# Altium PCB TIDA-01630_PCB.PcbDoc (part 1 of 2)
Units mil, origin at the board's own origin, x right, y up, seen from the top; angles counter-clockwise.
Board outline 3155 x 2050 mil, 4 copper layers (Top Layer, Signal Layer 1, Signal Layer 2, Bottom Layer), stack 49.055 mil thick; 119 components, 66 nets, 330 pads, 436 vias.
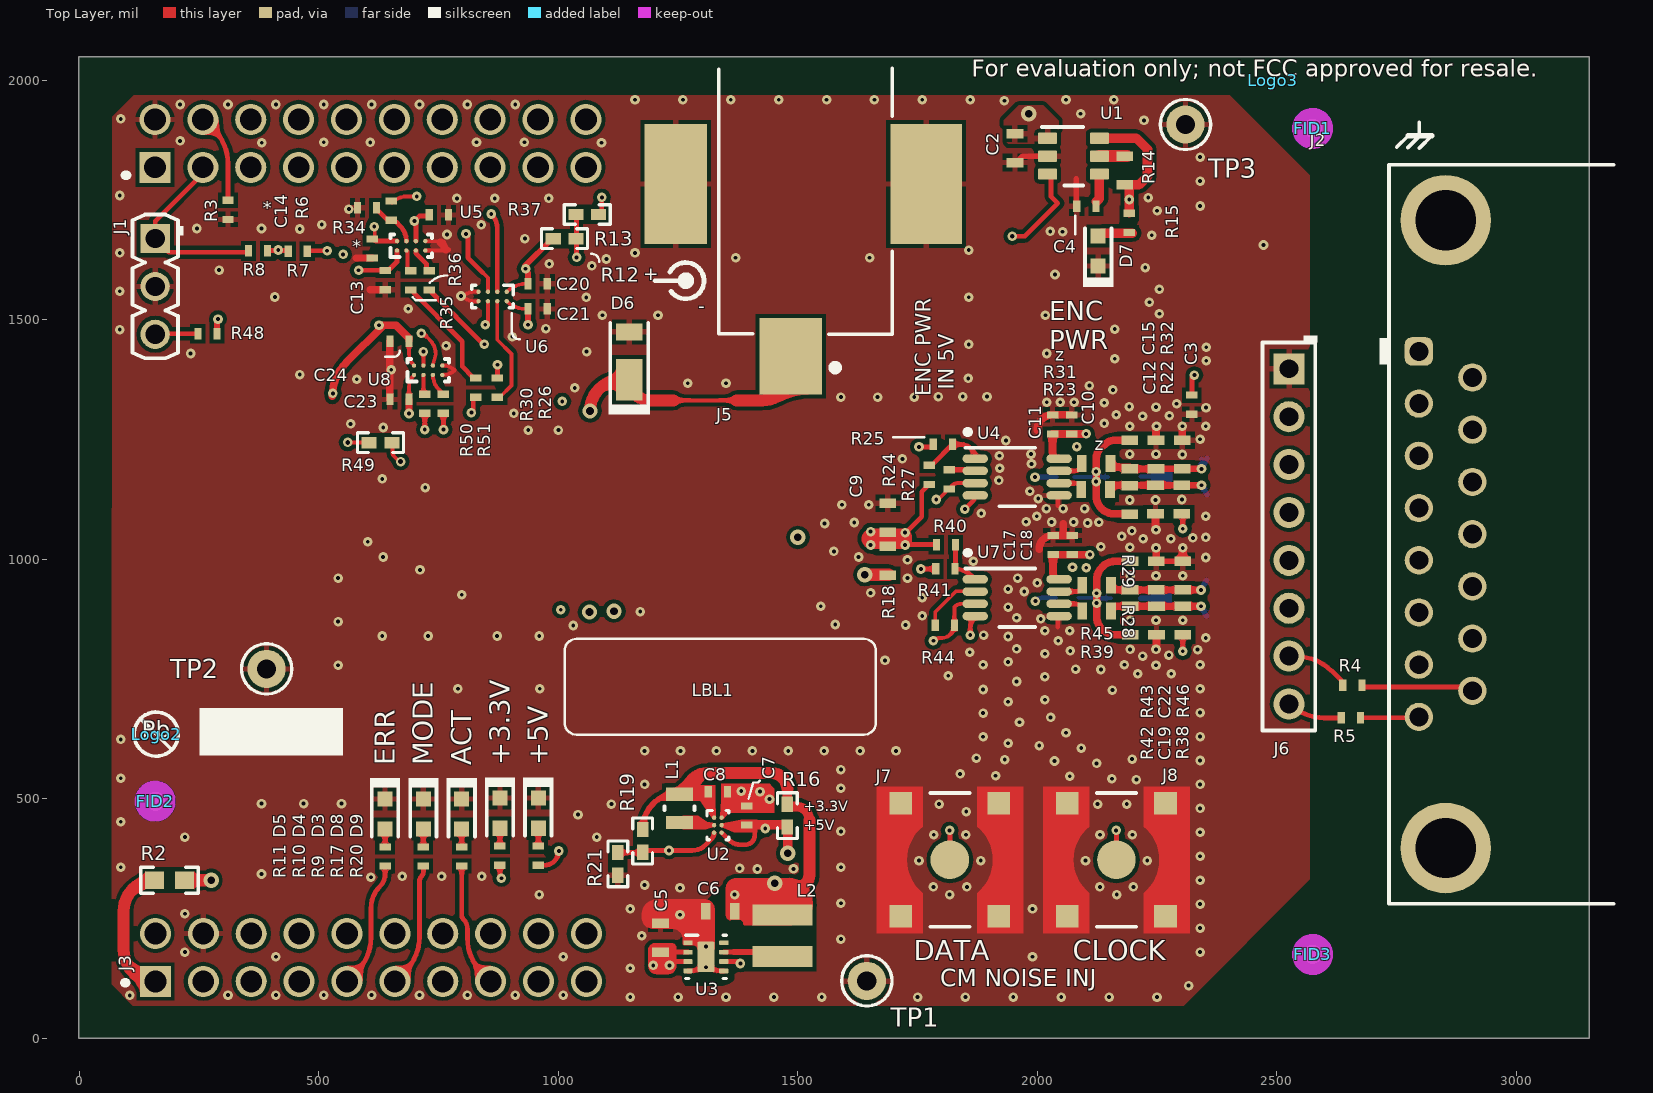
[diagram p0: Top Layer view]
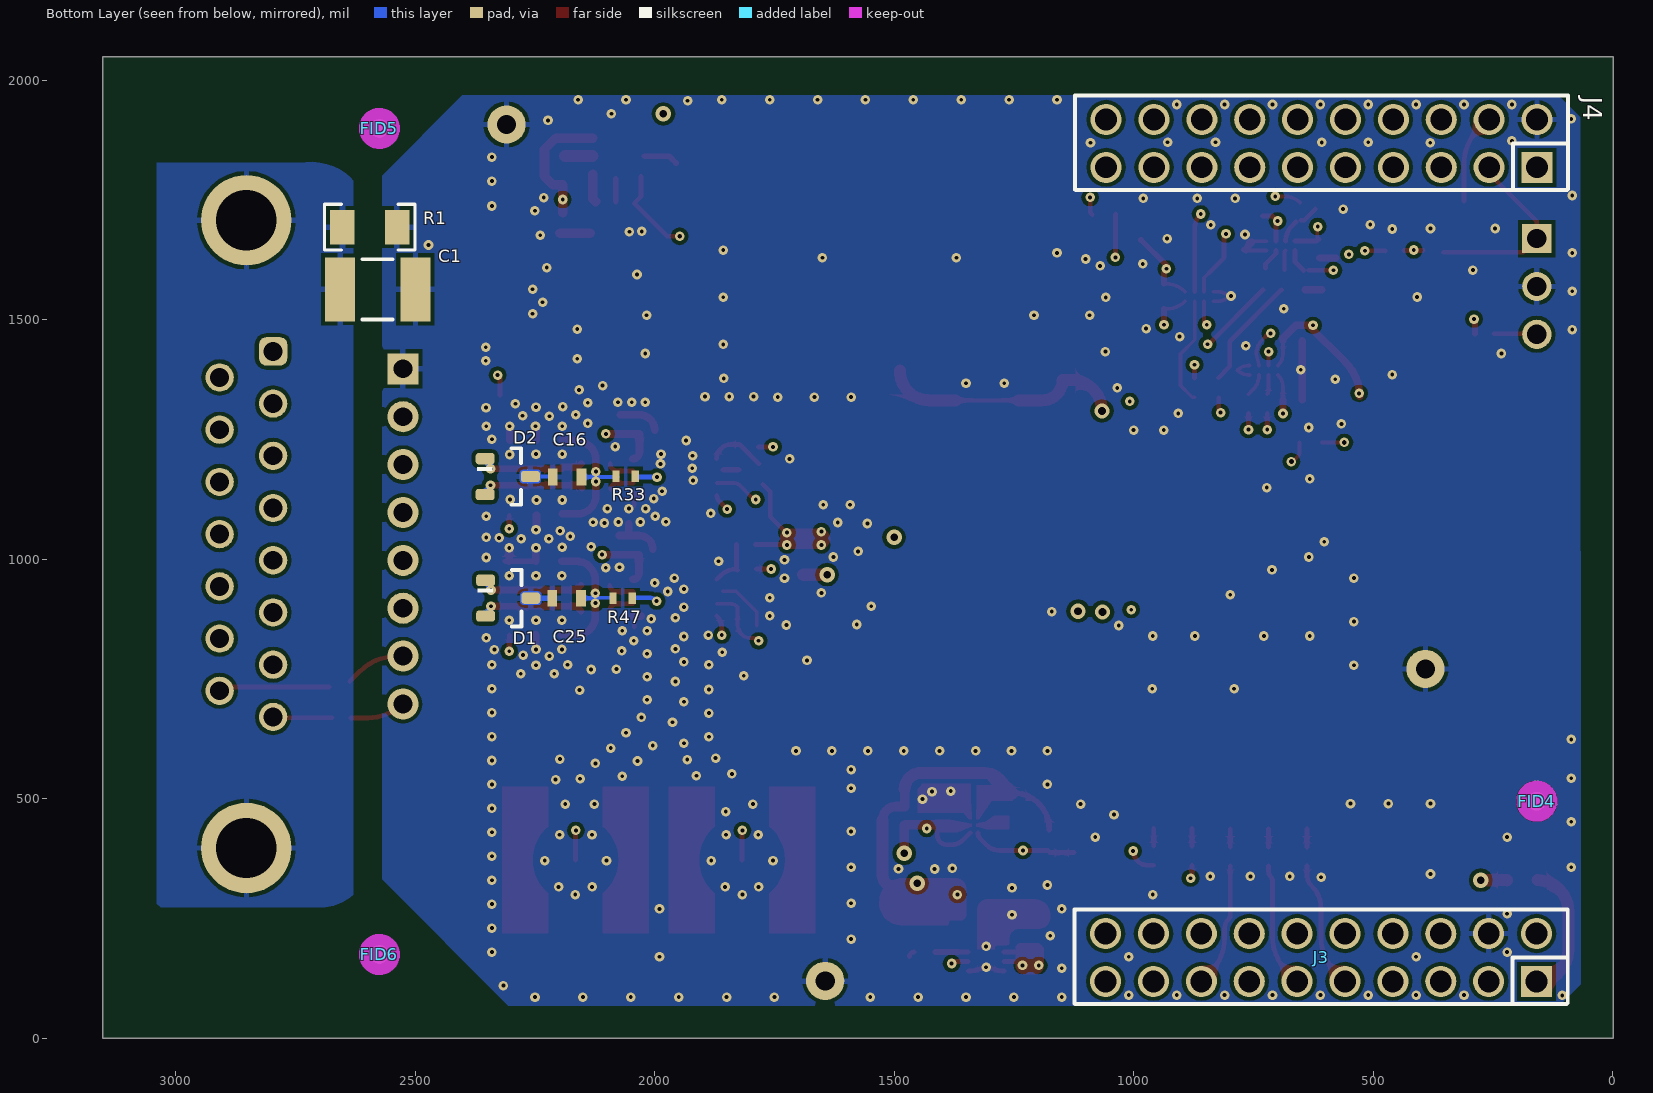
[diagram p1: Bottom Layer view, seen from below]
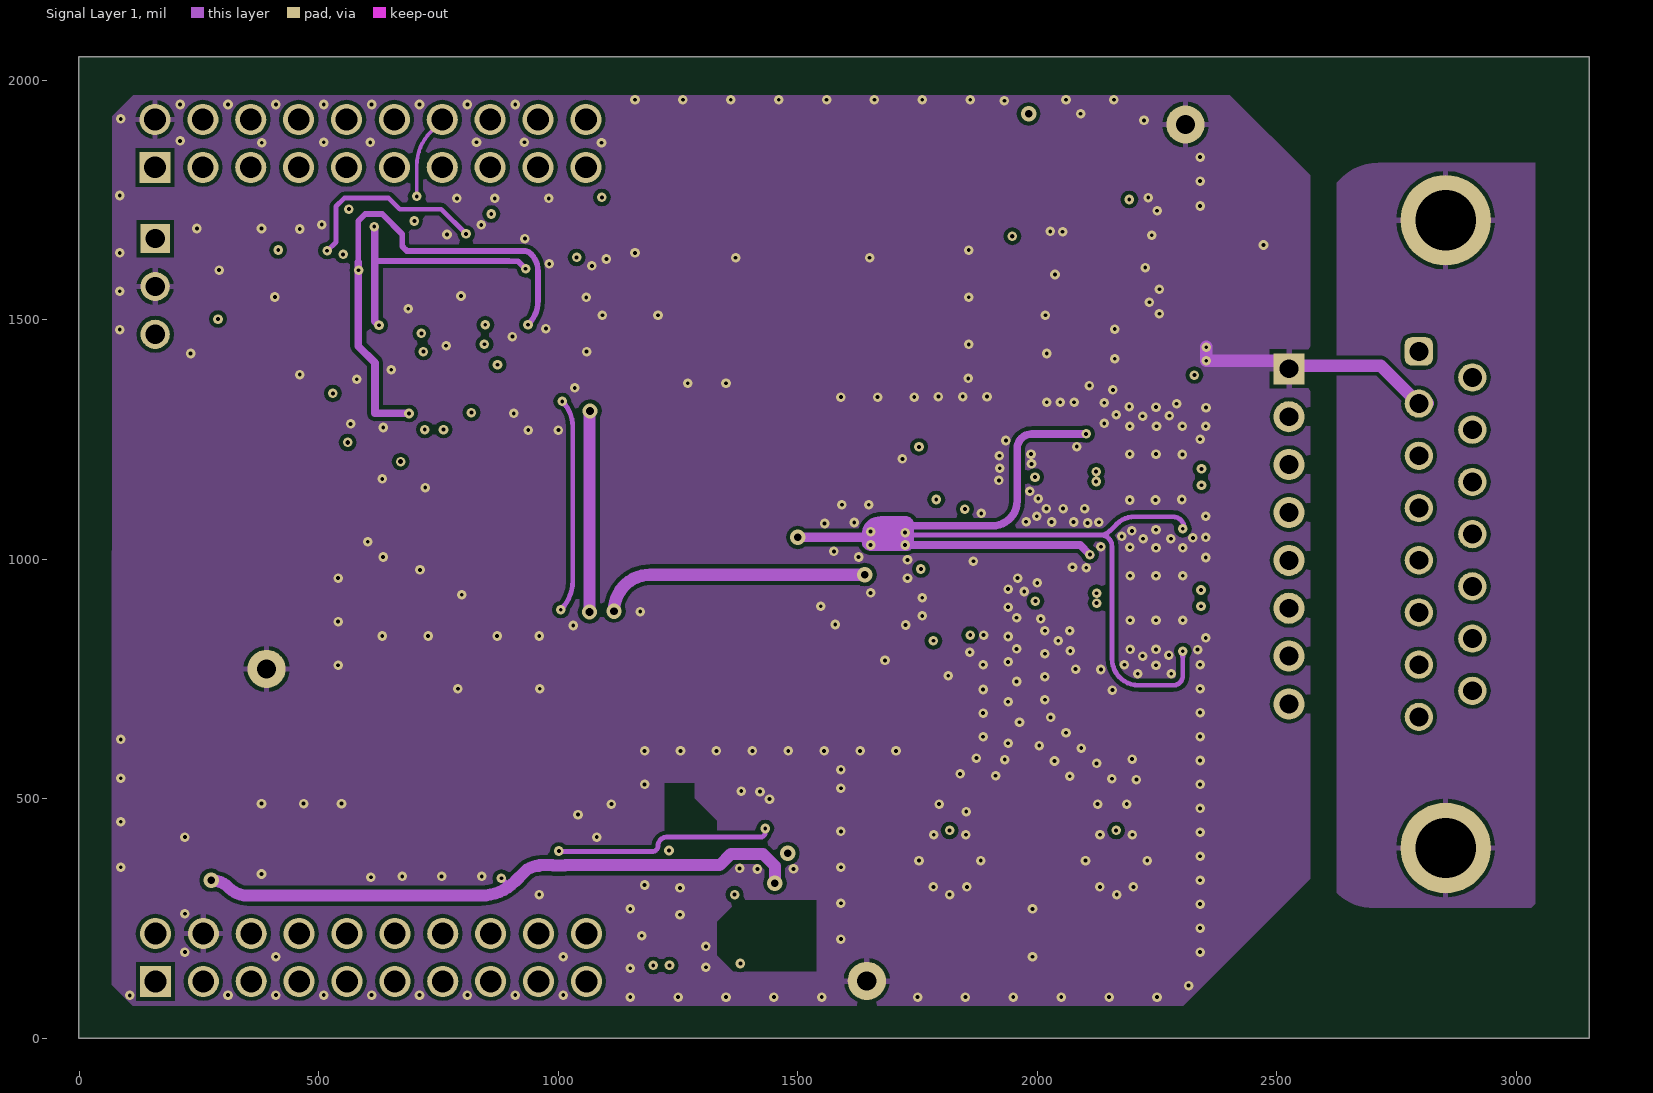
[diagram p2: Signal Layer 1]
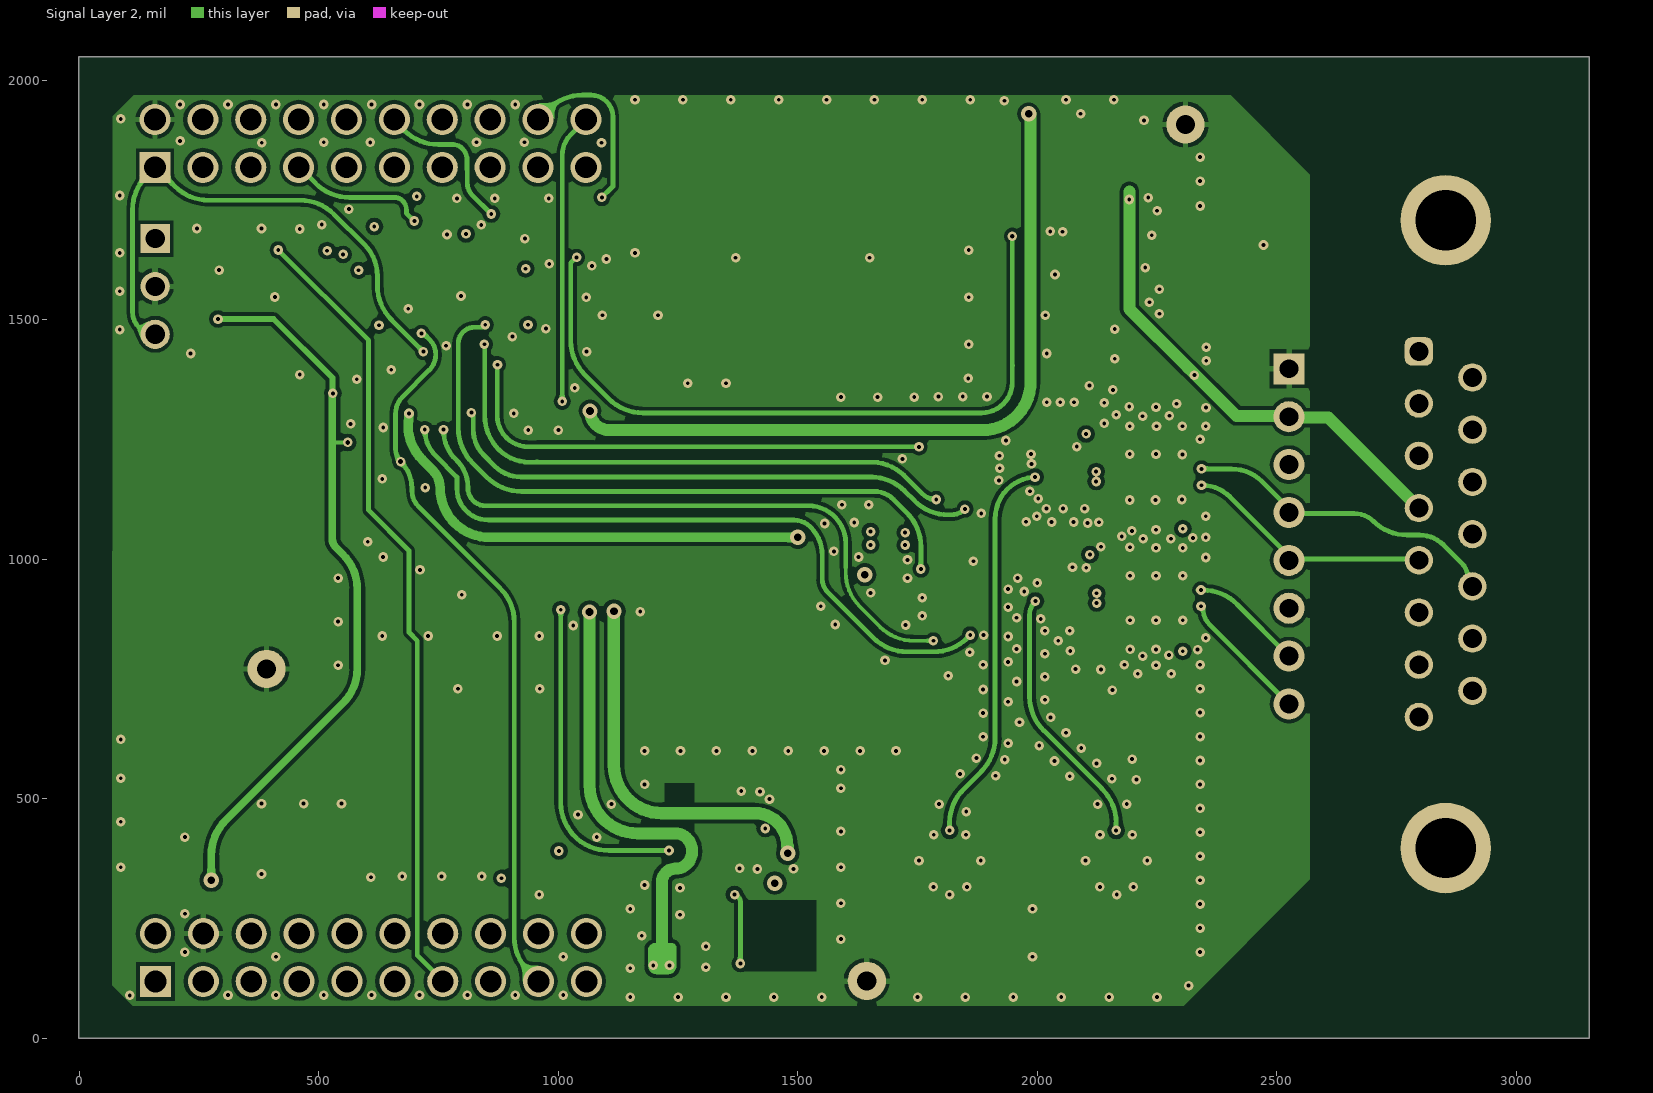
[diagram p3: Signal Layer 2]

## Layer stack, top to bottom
Top Solder: solder mask 0.9843, Solder Resist, Dk 3.5
Top Layer: signal copper 1.6929
Dielectric 1: prepreg 7.4803, FR-4, Dk 4.3
Signal Layer 1: signal copper 1.378
Dielectric 2: core 27.9528, FR-4, Dk 4.3
Signal Layer 2: signal copper 1.378
Dielectric 3: prepreg 7.4803, FR-4, Dk 4.3
Bottom Layer: signal copper 1.6929
Bottom Solder: solder mask 0.9843, Solder Resist, Dk 3.5

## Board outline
-2,0 3153,0 3153,2050 -2,2050

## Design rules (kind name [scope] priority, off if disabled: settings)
AcuteAngle [All] p1: minimum=3.00000000000000E+0001 checktracksonly=FALSE
AssemblyTestPointUsage [All] p1: valid=2
BoardOutlineClearance BoardOutlineClearance_MountingHoles [OnCopper and InComponentClass('Mounting Holes')] p1: gap=40 ignorepadtopadclearanceinfootprint=FALSE
BoardOutlineClearance BoardOutlineClearance_Poly [OnCopper and IsPoly] p2: gap=25 ignorepadtopadclearanceinfootprint=FALSE
BoardOutlineClearance [OnCopper and Not InComponentClass('Logo') and not InComponentClass('FiducialMark') and not InRegion(1000,500,4000,800) and not InPoly] p3: gap=75 ignorepadtopadclearanceinfootprint=FALSE
Clearance Clearance_partu4_u7 [((Component =U4)or (Component= U7))] p1: gap=7.8 ignorepadtopadclearanceinfootprint=FALSE except(0: Arc-Hole Track-Hole SMDPad-Hole THPad-Hole Via-Hole Fill-Hole Poly-Hole Region-Hole Text-Hole)
Clearance Clearance_partu2 [((Component =U2))] p2: gap=6.2 ignorepadtopadclearanceinfootprint=FALSE except(0: Arc-Hole Track-Hole SMDPad-Hole THPad-Hole Via-Hole Fill-Hole Poly-Hole Region-Hole Text-Hole)
Clearance Clearance_fiducial [((Component =FID1) or (Component =FID2) or (Component =FID3) or (Component =FID4) or (Component =FID5) or (Component =FID6))] p3: gap=0 ignorepadtopadclearanceinfootprint=FALSE
Clearance Clearance_netsu2 [(Net = '3V3') or (Net = '3V3_ENABLE_5V') vs (Net = 'NetL1_2') or (Net = '5VUNFILTERED')] p4: gap=5.7 ignorepadtopadclearanceinfootprint=FALSE except(0: Arc-Hole Track-Hole SMDPad-Hole THPad-Hole Via-Hole Fill-Hole Poly-Hole Region-Hole Text-Hole)
Clearance Clearance_Keepouts [((IsTrack Or IsArc) And Not InPoly) And IsFree and IsKeepOut vs ((IsTrack Or IsArc) And Not InPoly) And IsFree and IsKeepOut] p5: gap=0 ignorepadtopadclearanceinfootprint=FALSE
Clearance Clearance_Poly [InPolygon] p6: gap=8 ignorepadtopadclearanceinfootprint=FALSE except(0: Arc-Hole Track-Hole SMDPad-Hole THPad-Hole Via-Hole Fill-Hole Poly-Hole Region-Hole Text-Hole)
Clearance Clearance_part [Not IsNetTieComponent vs Not IsNetTieComponent] p7: gap=8 ignorepadtopadclearanceinfootprint=FALSE except(0: Arc-Hole Track-Hole SMDPad-Hole THPad-Hole Via-Hole Fill-Hole Poly-Hole Region-Hole Text-Hole)
ComponentClearance ComponentClearance_MountingHoles_FiducialMarks [InComponentClass('Mounting Holes') vs InComponentClass('FiducialMark')] p1: gap=50 collisioncheckmode=3 verticalgap=10 showdistances=FALSE
ComponentClearance ComponentClearance_Shunt [InComponentClass('Header') vs InComponentClass('Shunt')] p2: gap=0 collisioncheckmode=3 verticalgap=0 showdistances=FALSE
ComponentClearance ComponentClearance_Logo [InComponentClass('Logo')] p3: gap=20 collisioncheckmode=3 verticalgap=10 showdistances=FALSE
ComponentClearance ComponentClearance_ScrewToNut [(HasFootprint('NY PMS 440 0025 PH')) vs (HasFootprint('Keystone_1902C'))] p4: gap=5 collisioncheckmode=3 verticalgap=10 showdistances=FALSE
ComponentClearance ComponentClearance_MountingHoles [InComponentClass('Mounting Holes')] p5: gap=250 collisioncheckmode=3 verticalgap=100000 showdistances=FALSE
ComponentClearance ComponentClearance_SmallPassives [HasFootprint('0201*') or HasFootprint('0402*') or HasFootprint('0508') or HasFootprint('0603*') or HasFootprint('0612') or HasFootprint('0805*') or HasFootprint('0815*') or HasFootprint('0830*') or HasFootprint('1206*') or HasFootprint('1210*') or HasFootprint('1808*') or HasFootprint('1812*') or HasFootprint('1825*') or HasFootprint('2010*') or HasFootprint('2220*') or HasFootprint('2225*') or HasFootprint('2512*') or HasFootprint('2728*') or HasFootprint('3518*') vs HasFootprint('0201*') or HasFootprint('0402*') or HasFootprint('0508') or HasFootprint('0603*') or HasFootprint('0612') or HasFootprint('0805*') or HasFootprint('0815*') or HasFootprint('0830*') or HasFootprint('1206*') or HasFootprint('1210*') or HasFootprint('1808*') or HasFootprint('1812*') or HasFootprint('1825*') or HasFootprint('2010*') or HasFootprint('2220*') or HasFootprint('2225*') or HasFootprint('2512*') or HasFootprint('2728*') or HasFootprint('3518*')] p6: gap=14.96 collisioncheckmode=3 verticalgap=10 showdistances=FALSE
ComponentClearance ComponentClearance_THtoSMT [IsThruComponent vs IsSMTComponent] p7: gap=15 collisioncheckmode=3 verticalgap=30 showdistances=FALSE
ComponentClearance ComponentClearance_THtoTH [IsThruComponent vs IsThruComponent] p8: gap=30 collisioncheckmode=3 verticalgap=30 showdistances=FALSE
ComponentClearance [Not IsNetTieComponent vs Not IsNetTieComponent] p9: gap=30 collisioncheckmode=3 verticalgap=10 showdistances=FALSE
DiffPairsRouting [All] p1: maxlimit=100 minlimit=10 mostfreqgap=10 toplayer_minwidth=10 toplayer_maxwidth=15 toplayer_prefwidth=15 midlayer1_minwidth=10 midlayer1_maxwidth=15 midlayer1_prefwidth=15 midlayer2_minwidth=10 midlayer2_maxwidth=15 midlayer2_prefwidth=15 bottomlayer_minwidth=10 bottomlayer_maxwidth=15 bottomlayer_prefwidth=15 maxuncoupledlength=1000
FabricationTestPointUsage TestPointUsage [All] p1: valid=2 allowmultiple=FALSE
FabricationTestpoint Testpoint [All] p1: side=3 testpointundercomponent=TRUE minsize=40 maxsize=100 preferedsize=60 minholesize=0 maxholesize=40 preferedholesize=32 testpointgrid=1 allowsidetop=TRUE allowsidebottom=TRUE usegrid=TRUE gridtolerance=0.01
FanoutControl Fanout_LCC [IsLCC] p1: bgadir=Out bgaviamode=Centered fanoutstyle=Auto fanoutdirection=Alternating viagrid=1 // Fanout_LCC (Default Rule)
FanoutControl Fanout_BGA [IsBGA] p2: bgadir=Out bgaviamode=Centered fanoutstyle=Auto fanoutdirection=Alternating viagrid=1 // Fanout_BGA (Default Rule)
FanoutControl Fanout_Default [All] p4: bgadir=Out bgaviamode=Centered fanoutstyle=Auto fanoutdirection=Alternating viagrid=1 // Fanout_Default (Default Rule)
FanoutControl Fanout_Small [(CompPinCount < 5)] p5: bgadir=Out bgaviamode=Centered fanoutstyle=Auto fanoutdirection=OutThenIn viagrid=1 // Fanout_Small (Default Rule)
HoleSize [All] p1: absolutevalues=TRUE maxlimit=251 minlimit=7.87 maxpercent=80.000 minpercent=20.000
HoleToHoleClearance [All] p1: gap=10 allowstackedmicrovias=FALSE
MinimumAnnularRing MinimumAnnularRing_ThermalPadVias [IsVia and InAnyComponent] p1: minimumring=5
MinimumAnnularRing [All] p2: minimumring=5
MinimumSolderMaskSliver MinimumSolderMaskSliver_Logo [InComponentClass('Logo') vs InComponentClass('Logo')] p1: minsoldermaskwidth=0.7
MinimumSolderMaskSliver [All] p2: minsoldermaskwidth=2
NetAntennae [All] p1: netantennaetolerance=4
PlaneClearance [All] p1: clearance=10
PlaneConnect [All] p1: planeconnectstyle=Relief reliefexpansion=10 reliefentries=4 reliefconductorwidth=14 reliefairgap=8
PolygonConnect PolygonConnect_Power [IsVia  Or InLayerStackRegion('')] p1: connectstyle=Direct reliefconductorwidth=10 reliefentries=4 polygonreliefangle="90 Angle" airgapwidth=10
PolygonConnect [All] p2: connectstyle=Relief reliefconductorwidth=12 reliefentries=4 polygonreliefangle="90 Angle" airgapwidth=8
RoutingCorners [All] p1: cornerstyle=Round minsetback=100 maxsetback=100
RoutingVias ThermalPadVias [IsVia and InAnyComponent] p1: holewidth=8 width=20 viastyle="Through Hole" minholewidth=7.87 minwidth=18 maxholewidth=13 maxwidth=24
RoutingVias [All] p2: holewidth=10 width=20 viastyle="Through Hole" minholewidth=7.87 minwidth=18 maxholewidth=40 maxwidth=60
SilkToBoardRegionClearance [Not ((IsComment or IsDesignator) And (Hide <> 'False')) and not InRegion(1000,500,4000,800)] p1:
SilkToSilkClearance SilkToSilkClearance_Pb-FreeLogo [(HasFootprint('Pb-Free_Overlay_Medium') OR HasFootprint('Pb-Free_Overlay_Small')) vs (HasFootprint('Pb-Free_Overlay_Medium') OR HasFootprint('Pb-Free_Overlay_Small'))] p1: silktosilkclearance=0
SilkToSilkClearance [All] p2: silktosilkclearance=2
SilkToSolderMaskClearance [InNet('NetC24_1') Or InNet('NetC15_1')] p1: minsilkscreentomaskgap=0 clearancetoexposedcopper=TRUE
SilkToSolderMaskClearance SilkToComponentPadClearance [(IsPad or IsFill or IsRegion) and InAnycomponent] p2: minsilkscreentomaskgap=3 clearancetoexposedcopper=TRUE
SilkToSolderMaskClearance "Silk to Solder Mask Opening" [All] p3: minsilkscreentomaskgap=2 clearancetoexposedcopper=FALSE
SolderMaskExpansion [All] p1: expansion=1.97
ViasUnderSMD [IsNetTieComponent] p1: allowed=TRUE
Width [All] p1: maxlimit=100 minlimit=6 preferedwidth=10 checkconnectedcopper=TRUE
11 further rules are at their usual default settings.

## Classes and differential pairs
component class TIDA-01630_Transceivers: C10 C11 C12 C13 C14 C15 C16 C17 C18 C19 C20 C21 C22 C23 C24 C25 C28 J7 J8 NT? R22 R23 R24 R25 R26 R27 R28 R29 R30 R31 R32 R33 R34 R35 R36 R37 R38 R39 R40 R41 R42 R43 R44 R45 R46 R47 R48 R49 R50 R51 U4 U5 U6 U7 U8
component class TIDA-01630_PowerSupply: C2 C3 C4 C5 C6 C7 C8 C9 D7 D8 D9 L1 L2 R12 R13 R14 R15 R16 R17 R18 R19 R20 R21 U1 U2 U3
component class TIDA-01630_Interface: C1 D1 D2 D3 D4 D5 D6 J1 J2 J3 J4 J5 J6 R1 R2 R3 R4 R5 R6 R7 R8 R9 R10 R11 TP1 TP2 TP3
component class Header: J1 J6
component class Label: LBL1
component class AssemblyNote: ZZ1 ZZ2 ZZ3 ZZ4
component class FiducialMark: FID1 FID2 FID3 FID4 FID5 FID6
component class TIDA-01630_EVM_Hardware: FID1 FID2 FID3 FID4 FID5 FID6 LBL1 Logo2 Logo3 ZZ1 ZZ2 ZZ3 ZZ4
differential pair D_CLK_: +CLK_P -CLK_N
differential pair D_DATA_: +DATA_P -DATA_N

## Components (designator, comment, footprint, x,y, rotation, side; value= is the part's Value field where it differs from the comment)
C1 "1812GC102KAT1A" 1812_220 2578.61,1564.03 r180 bottom value=1000pF
C2 "Capacitor" 0603S 1953.42,1858.66 r270 top value=1uF
C3 "GRM155R6YA225ME11D" 0402_070 2323,1323 r270 top value=2.2uF
C4 "GRM155R71H471KA01D" 0402S 2102.59,1737.67 r0 top value=470pF
C5 "Capacitor" 0603S 1213,210 r90 top value=10uF
C6 "Capacitor" 0603S 1338,265 r180 top value=22uF
C7 "Capacitor" 0402_065S 1393,465 r90 top value=4.7uF
C8 "885012105013" 0402S 1333,515 r0 top value=2.2uF
C9 "Capacitor" 0603S 1688,1087 r90 top value=22uF
C10 "Capacitor" 0402S 2072,1281.76 r90 top value=1uF
C11 "Capacitor" 0402S 2032,1281.76 r90 top value=0.1uF
C12 "Capacitor" 0603S 2247,1125 r90 top value=220pF
C13 "Capacitor" 0402S 638.49,1583.17 r90 top value=0.1uF
C14 "Capacitor" 0402S 611.37,1649.31 r90 top value=0.1uF
C15 "Capacitor" 0603S 2248,1219 r90 top value=220pF
C16 "Capacitor" 0603S 2183,1172 r0 bottom value=470pF
C17 "Capacitor" 0402S 2033,1030 r90 top value=1uF
C18 "Capacitor" 0402S 2073,1030 r90 top value=0.1uF
C19 "Capacitor" 0603S 2249,872.33 r90 top value=220pF
C20 "Capacitor" 0402S 956.54,1575.55 r180 top value=0.1uF
C21 "Capacitor" 0402S 956.54,1523.05 r180 top value=0.1uF
C22 "Capacitor" 0603S 2248.73,966.16 r90 top value=220pF
C23 "Capacitor" 0402S 668,1334 r0 top value=0.1uF
C24 "Capacitor" 0402S 668,1456 r0 top value=0.1uF
C25 "Capacitor" 0603S 2184,919 r0 bottom value=470pF
D1 "Diode_TVS_Bi_Dual" SOT-23 2306,919 r180 bottom value=7V
D2 "Diode_TVS_Bi_Dual" SOT-23 2307,1173 r180 bottom value=7V
D3 "LED_A2_K1" WL-SMCW_Blue 798,468.37 r270 top value=Blue
D4 "LED_A2_K1" WL-SMCW_GREEN 718,468.37 r270 top value=Green
D5 "LED_A2_K1" WL-SMCW_RED 638,468.37 r270 top value=Red
D6 "DIODE" PowerDI123 1148,1425 r90 top value=40V
D7 "LED_A2_K1" WL-SMCW_GREEN 2127.3,1644.02 r90 top value=Green
D8 "LED_A2_K1" WL-SMCW_GREEN 878,470 r270 top value=Green
D9 "LED_A2_K1" WL-SMCW_GREEN 958,470 r270 top value=Green
FID1 "Fiducial" Fiducial10-20 2575,1900 r0 top
FID2 "Fiducial" Fiducial10-20 158,495 r0 top
FID3 "Fiducial" Fiducial10-20 2575,175 r0 top
FID4 "Fiducial" Fiducial10-20 158,495 r180 bottom
FID5 "Fiducial" Fiducial10-20 2575,1900 r180 bottom
FID6 "Fiducial" Fiducial10-20 2575,175 r180 bottom
J1 "Header_3x1" FCI_68001-403HLF 158,1570 r270 top
J2 "618015231121" Wurth_618015231121 3226.83,1052.73 r0 top
J3 "Receptacle_10x2" CONN_SSW-110-23-F-D 608.49,168.62 r180 bottom locked
J4 "Receptacle_10x2" CONN_SSW-110-23-F-D 607.49,1868.62 r180 bottom
J5 "CONN_DC JACK" Switchcraft_RASM722 1515,2050 r180 top
J6 "Header_8x1" SULLINS_PEC08SAAN 2525.63,1047.98 r270 top
J7 "SMA_Contact1_GND2345" Linx_CONSMA001-SMD-G 1817.59,372.51 r0 top
J8 "SMA_Contact1_GND2345" Linx_CONSMA001-SMD-G 2165.34,372.51 r180 top
L1 "Inductor_Iron" WE-PMI_0805LR 1253,480 r270 top value=1uH
L2 "Inductor_Iron" XFL3012 1468,214 r90 top value=2.2uH
LBL1 "Label" Label_650x200 1338,734 r0 top
Logo2 "Pb-Free Symbol" Pb-Free_Overlay_Small 160,635 r0 top
Logo3 "FCC disclaimer" FCC_disclaimer 2491.49,2000.85 r0 top
R1 "Resistor" 1206 2595.31,1693.75 r0 bottom value=2.2Meg
R2 "Resistor" 0603 188,330 r180 top value=0
R3 "Resistor" 0402S 310,1730 r270 top value=150k
R4 "Resistor" 0402S 2658.08,737.24 r180 top value=0
R5 "Resistor" 0402S 2654.82,669.45 r0 top value=0
R6 "CRCW040222R0JNED" 0402S 650.59,1728.19 r270 top value=22
R7 "CRCW040222R0JNED" 0402S 455.66,1643.76 r180 top value=22
R8 "Resistor" 0402S 372.78,1644.13 r180 top value=0
R9 "Resistor" 0402S 798,379.57 r270 top value=2.2k
R10 "Resistor" 0402S 718,379.57 r270 top value=2.2k
R11 "Resistor" 0402S 638,379.57 r270 top value=4.7k
R12 "Resistor" 0402 1012.79,1669.73 r180 top value=10k
R13 "Resistor" 0402 1060.41,1720.32 r180 top value=0
R14 "Resistor" 0603S 2182.96,1812.11 r270 top value=1.0k
R15 "Resistor" 0402S 2192.45,1702.78 r270 top value=30k
R16 "Resistor" 0402 1478,465 r90 top value=0
R17 "Resistor" 0402S 878,381.2 r270 top value=2.2k
R18 "Resistor" 0603S 1688,997 r90 top value=1.0
R19 "Resistor" 0402 1176,412 r90 top value=10k
R20 "Resistor" 0402S 958,381.2 r270 top value=4.7k
R21 "Resistor" 0402 1124,364 r90 top value=10k
R22 "CRCW06031K00JNEA" 0603S 2302,1125 r270 top value=1.0k
R23 "Resistor" 0603S 2122,1146 r0 top value=0
R24 "CRCW04024K70JNED" 0402S 1774.43,1176.56 r270 top value=4.7k
R25 "CRCW040222R0JNED" 0402S 1803,1240 r0 top value=22
R26 "Resistor" 0402S 872.71,1358.65 r90 top value=0
R27 "Resistor" 0402S 1816.58,1167.15 r90 top value=0
R28 "CRCW0603110RFKEA" 0603S 2193,1124 r90 top value=110
R29 "CRCW0603110RFKEA" 0603S 2193,1219 r90 top value=110
R30 "Resistor" 0402S 827.7,1358.65 r270 top value=0
R31 "Resistor" 0603S 2123,1200 r0 top value=0
R32 "CRCW06031K00JNEA" 0603S 2303,1219 r270 top value=1.0k
R33 "Resistor" 0402S 2060.72,1173.24 r0 bottom value=0
R34 "CRCW04024K70JNED" 0402S 600.29,1734.26 r180 top value=4.7k
R35 "Resistor" 0402S 691.17,1582.87 r90 top value=47
R36 "Resistor" 0402S 730.17,1582.87 r90 top value=47
R37 "CRCW04024K70JNED" 0402S 750.37,1719.29 r180 top value=4.7k
R38 "Resistor" 0603S 2304,872.33 r270 top value=10k
R39 "Resistor" 0603S 2124,892 r0 top value=0
R40 "CRCW04024K70JNED" 0402S 1809.43,1030.82 r180 top value=4.7k
R41 "CRCW040222R0JNED" 0402S 1808,980 r0 top value=22
R42 "Resistor" 0603S 2194,872.33 r270 top value=59.0
R43 "Resistor" 0603S 2193.73,966.16 r270 top value=59.0
R44 "Resistor" 0402S 1807,862 r180 top value=0
R45 "Resistor" 0603S 2124,946 r0 top value=0
R46 "Resistor" 0603S 2303.73,966.16 r270 top value=10k
R47 "Resistor" 0402S 2067.02,919.24 r0 bottom value=0
R48 "CRCW04024K70JNED" 0402S 267.15,1471.32 r0 top value=4.7k
R49 "CRCW04024K70JNED" 0402 628.47,1243.65 r180 top value=4.7k
R50 "Resistor" 0402S 721,1325 r90 top value=47
R51 "Resistor" 0402S 760,1325 r90 top value=47
TP1 "5001" Keystone5001 1644.09,119.71 r90 top
TP2 "5001" Keystone5001 390.6,771.25 r90 top
TP3 "5001" Keystone5001 2309.52,1908.2 r90 top
U1 "TPS22810DBV" DBV0006A_N 2075.73,1842.05 r0 top
U2 "TPS6124xYFF" YFF0006AEAE 1333,445 r0 top
U3 "TI-TPS62162DSG8-1600X900TP" DSG0008A 1308,170 r0 top
U4 "THVD1550DGKR" DGK0008A_N 1958,1172 r0 top
U5 "TI-SN74XVC2T45-YZP0008A-8" YZP0008ADAD 692.49,1654.86 r90 top
U6 "TI-SN74XVC2T45-YZP0008A-8" YZP0008ADAD 862.54,1549.05 r270 top
U7 "THVD1550DGKR" DGK0008A_N 1958,920 r0 top
U8 "TI-SN74XVC2T45-YZP0008A-8" YZP0008ADAD 728,1395 r90 top
ZZ1 "This Assembly Note is for PCB labels only" AssemblyNoteLabel 184,3925 r0 top
ZZ2 "These assemblies are ESD sensitive, ESD precautions shall be observed." AssemblyNote 186,3833.11 r0 top
ZZ3 "These assemblies must be clean and free from flux and all contaminants. Use of no clean flux is not acceptable." AssemblyNote 186,3744.56 r0 top
ZZ4 "These assemblies must comply with workmanship standards IPC-A-610 Class 2, unless otherwise specified." AssemblyNote 186,3656 r0 top

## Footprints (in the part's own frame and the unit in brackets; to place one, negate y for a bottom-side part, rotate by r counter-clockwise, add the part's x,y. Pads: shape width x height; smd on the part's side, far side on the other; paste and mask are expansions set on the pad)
0402 [mm] "0402 from SM-752 data"
  rect 0.8x0.6 smd: 1(-0.6,0) 2(0.6,0)
  silkscreen extent -1.22,-0.52 1.22,0.52, body extent -0.55,-0.3 0.55,0.3, height 0.6
0402_065S [mil] "Based on C0402S footprint from PADS legacy"
  rect 15x24 smd: 1(-20,0) 2(20,0)
  body extent -22,-12 22,12, height 26
0402_070 [mil] "SMD, 2-Leads, Body 1.2x0.7mm, Height 0.7mm"
  rect 15x24 smd: 1(-20,0) 2(20,0)
  body extent -24,-14 24,14, height 28
0402S [mil] "Based on C0402S footprint from PADS legacy"
  rect 15x24 smd: 1(-20,0) 2(20,0)
  body extent -22,-12 22,12, height 24
0603 [mm] "0603 from SM-752 data"
  rect 1x0.95 smd: 1(-0.8,0) 2(0.8,0)
  silkscreen extent -1.52,-0.69 1.52,0.69, body extent -0.87,-0.47 0.87,0.47, height 1
0603S [mil]
  rect 20x35 smd: 1(-30,0) 2(30,0)
  body extent -34,-19 34,19, height 39
1206 [mm] "1206 from SM-752 data"
  rect 1.3x1.85 smd: 1(-1.45,0) 2(1.45,0)
  silkscreen extent -2.4,-1.21 2.4,1.21, body extent -1.7,-0.9 1.7,0.9, height 1.35
1812_220 [mm] "1812"
  rect 1.6x3.4 smd: 1(-2,0) 2(2,0)
  silkscreen extent -0.8,-1.6 0.8,1.6, body extent -2.4,-1.7 2.4,1.7, height 2.2
AssemblyNote [mil] "Assembly Note"
AssemblyNoteLabel [mil] "Assembly Note for PCB Labels"
CONN_SSW-110-23-F-D [mm] "SAMTEC"
  rect 1.65x1.65 hole 1.15: 1(11.43,-1.27)
  round 1.65 hole 1.15: 2(11.43,1.27) 3(8.89,-1.27) 4(8.89,1.27) 5(6.35,-1.27) 6(6.35,1.27) 7(3.81,-1.27) 8(3.81,1.27) 9(1.27,-1.27) 10(1.27,1.27) 11(-1.27,-1.27) 12(-1.27,1.27) 13(-3.81,-1.27) 14(-3.81,1.27) 15(-6.35,-1.27) 16(-6.35,1.27) 17(-8.89,-1.27) 18(-8.89,1.27) 19(-11.43,-1.27) 20(-11.43,1.27)
  silkscreen extent -13.08,-2.46 13.08,2.54, body extent -13,-2.51 13,2.54, height 8.59
DBV0006A_N [mm] "SOT23, 6-Leads, Body 2.9x1.6mm, Pitch 0.95mm, Lead Span 2.8mm, IPC Medium Density"
  rrect17% 1x0.6 smd: 1(-1.375,0.95) 2(-1.375,0) 3(-1.375,-0.95) 4(1.375,-0.95) 5(1.375,0) 6(1.375,0.95)
  silkscreen extent -1.68,-1.55 0.5,1.55, body extent -1.42,-1.46 1.42,1.46, height 1.12
DGK0008A_N [mm] "TSOP, 8-Leads, Body 3x3mm, Pitch 0.65mm, IPC Medium Density"
  oval 1.35x0.45 smd: 1(-2.225,0.975) 2(-2.225,0.325) 3(-2.225,-0.325) 4(-2.225,-0.975) 5(2.225,-0.975) 6(2.225,-0.325) 7(2.225,0.325) 8(2.225,0.975)
  silkscreen extent -2.75,-1.55 0.95,1.55, body extent -2.45,-1.5 2.45,1.5, height 0.96
DSG0008A [mm] "SON, 8-Leads, Body 2x2mm, Pitch 0.5mm, Thermal Pad 1.6x0.9mm, TI Recommended"
  rrect40% 0.5x0.25 smd: 1(-0.95,0.75) 2(-0.95,0.25) 3(-0.95,-0.25) 4(-0.95,-0.75) 5(0.95,-0.75) 6(0.95,-0.25) 7(0.95,0.25) 8(0.95,0.75)
  rrect14% 0.9x0.7 on Top Paste: 9(0,-0.45) 9(0,0.45)
  rrect11% 0.9x1.6 smd paste-0.45: 9(0,0)
  silkscreen extent -1.07,-1.15 1.07,1.15, body extent -1,-1 1,1, height 0.77
FCC_disclaimer [mil]
FCI_68001-403HLF [mm] "Header, 2.54mm, 3x1, TH"
  rect 1.55x1.55 hole 1.02: 1(-2.54,0)
  round 1.55 hole 1.02: 2(0,0) 3(2.54,0)
  silkscreen extent -3.81,-1.21 3.81,1.5, body extent -3.81,-1.21 3.81,1.21, height 8.38
Fiducial10-20 [mm]
  round 1 smd mask+0.5: 1(0,0)
  Top Layer keep-out circle w1.178: c0,0 r0.5
Keystone5001 [mil] "For Keystone 500x miniature loop terminals"
  round 80 hole 40: 1(0,0)
  silkscreen extent -52,-52 52,52, body extent -49,-49 49,49, height 182
Label_650x200 [mil] "Thermal Transfer Label"
  round 1 on Mech13: 0(0,0)
  silkscreen extent -325,-100 325,100, body extent -325,-100 325,100, height 1
Linx_CONSMA001-SMD-G [mm] "SMD, 5-Leads, Body 7x7mm, Height 10.5mm"
  round 2.05 smd: 1(0,0)
  rect 1.2x1.2 smd: 2(-2.6,-3) 3(2.6,-3) 4(2.6,3) 5(-2.6,3)
  Top Layer region: -3.88,-3.88 -1.44,-3.88 -1.44,-1.761 -1.448,-1.761 -2.062,-0.974 -2.28,0 -2.062,0.974 -1.448,1.761 -1.448,1.761 -1.44,1.761 -1.44,3.88 -3.88,3.88
  Top Layer region: 3.88,-3.88 1.44,-3.88 1.44,-1.761 1.448,-1.761 2.062,-0.974 2.28,0 2.062,0.974 1.448,1.761 1.448,1.761 1.44,1.761 1.44,3.88 3.88,3.88
  silkscreen extent -1.04,-3.55 1.04,3.55, body extent -3.55,-3.55 3.55,3.55, height 10.5
Pb-Free_Overlay_Small [mil]
  silkscreen extent -46,-46 46,46
PowerDI123 [mm] "Diodes Inc recommended land pattern, document number DS30628 Rev. 6-2"
  rect 2.2x1.4 smd: 1(-1.275,0)
  rect 0.9x1.4 smd: 2(1.275,0)
  silkscreen extent -3.1,-1.09 1.76,1.09, body extent -2.38,-0.97 1.52,0.96, height 1
SOT-23 [mm] "SOT23, 3-Leads, Body 2.9x1.3mm, Pitch 0.95mm, Lead Span 2.5mm, IPC Medium Density"
  rrect50% 1x0.6 smd: 1(-1.2,0.95) 2(-1.2,-0.95) 3(1.2,0)
  silkscreen extent -1.62,-1.5 0.7,1.5, body extent -1.16,-1.45 1.21,1.45, height 1
SULLINS_PEC08SAAN [mm] "SULLINS"
  rect 1.65x1.65 hole 1: 1(-8.89,0)
  round 1.65 hole 1: 2(-6.35,0) 3(-3.81,0) 4(-1.27,0) 5(1.27,0) 6(3.81,0) 7(6.35,0) 8(8.89,0)
  silkscreen extent -10.67,-1.4 10.29,1.52, body extent -10.29,-1.33 10.29,1.33, height 8.38
Switchcraft_RASM722 [mm] "SMT, 3-Leads, Power Socket, R/A, Pin Size 2mm"
  rect 3.3x4.06 smd: 1(0.76,15.9)
  rect 3.81x6.35 smd: 2(-6.43,6.76)
  rect 3.3x6.35 smd: 3(6.86,6.76)
  silkscreen extent -4.63,0.63 4.57,16.68, body extent -7.6,0 7.6,16.9, height 11.08
WE-PMI_0805LR [mm] "WURTH"
  rect 0.7x1.45 smd: 1(-0.75,0) 2(0.75,0)
  silkscreen extent -0.1,-0.8 0.1,0.8, body extent -1.1,-0.7 1.1,0.7, height 1
WL-SMCW_Blue [mm] "SMD, 2-Leads, Body 1.6x0.8mm"
  rect 0.8x0.8 smd: 1(-0.8,0) 2(0.8,0)
  silkscreen extent -1.9,-0.8 1.2,0.8, body extent -0.85,-0.45 0.85,0.45, height 0.8
WL-SMCW_GREEN [mm] "WURTH"
  rect 0.8x0.8 smd: 1(-0.8,0) 2(0.8,0)
  silkscreen extent -1.9,-0.8 1.2,0.8, body extent -0.85,-0.45 0.85,0.45, height 0.8
WL-SMCW_RED [mm] "WURTH"
  rect 0.8x0.8 smd: 1(-0.8,0) 2(0.8,0)
  silkscreen extent -1.9,-0.8 1.2,0.8, body extent -0.85,-0.45 0.85,0.45, height 0.8
Wurth_618015231121 [mm] "Receptacle, D-Sub, 15 Position, R/A, TH"
  rrect50% 1.5x1.5 hole 1: 1(-10.92,9.695)
  round 1.5 hole 1: 2(-10.92,6.925) 3(-10.92,4.155) 4(-10.92,1.385) 5(-10.92,-1.385) 6(-10.92,-4.155) 7(-10.92,-6.925) 8(-10.92,-9.695) 9(-8.08,8.31) 10(-8.08,5.54) 11(-8.08,2.77) 12(-8.08,0) 13(-8.08,-2.77) 14(-8.08,-5.54) 15(-8.08,-8.31)
  round 4.8 hole 3.2: 16(-9.5,-16.65) 17(-9.5,16.65)
  silkscreen extent -13,-19.6 -0.6,19.6, body extent -12.5,-19.6 6,19.6, height 11.71
XFL3012 [mm] "Coilcraft"
  rect 1.12x3.2 smd: 1(-1.11,0) 2(1.11,0)
  body extent -1.6,-1.6 1.6,1.6, height 1.3
YFF0006AEAE [mm] "TI DSBGA 0.9x1.3mm"
  round 0.23 smd paste-0.13 mask+0.038: A1(-0.2,0.4) A2(0.2,0.4) B1(-0.2,0) B2(0.2,0) C1(-0.2,-0.4) C2(0.2,-0.4)
  silkscreen extent -0.58,-0.77 0.58,0.77, body extent -0.45,-0.65 0.45,0.65, height 0.63
YZP0008ADAD [mm] "BGA, 8-Leads, Body 1.9x0.9mm, Pitch 0.5mm"
  round 0.23 smd paste-0.12: A1(-0.25,0.75) A2(0.25,0.75) B1(-0.25,0.25) B2(0.25,0.25) C1(-0.25,-0.25) C2(0.25,-0.25) D1(-0.25,-0.75) D2(0.25,-0.75)
  silkscreen extent -0.6,-1.1 0.6,1.1, body extent -0.46,-0.96 0.46,0.96, height 0.51

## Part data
C1: library part CMP-0064918-2, "CAP, CERM, 1000 pF, 2000 V,+/- 10%, X7R, 1812", Cap_Case=1812, Manufacturer=AVX, Supplier Part Number 1=478-3000-1-ND, TempCo=X7R, Tolerance_%=10%, Value1=Unknown, Value2=2000V, ValueDisplayed=1000pF
C2: library part CMP-0006833-4, "CAP, CERM, 1 uF, 25 V, +/- 10%, X7R, 0603", Cap_Case=0603, Manufacturer="Wurth Elektronik", PartNumber=885012206076, Supplier Part Number 1=732-7994-1-ND, TempCo=X7R, Tolerance_%=10%, Value1=Unknown, Value2=25V, ValueDisplayed=1uF
C3: library part CMP-0006621-2, "CAP, CERM, 2.2 uF, 35 V, +/- 20%, X5R, 0402", Cap_Case=0402, Manufacturer=MuRata, TempCo=X5R, Tolerance_%=20%, Value1=Unknown, Value2=35V, ValueDisplayed=2.2uF
C4: library part CMP-0006691-2, "CAP, CERM, 470 pF, 50 V, +/- 10%, X7R, 0402", Cap_Case=0402, Manufacturer=MuRata, Supplier Part Number 1=490-1300-1-ND, TempCo=X7R, Tolerance_%=10%, Value1=Unknown, Value2=50V, ValueDisplayed=470pF
C5: library part CMP-0007007-5, "CAP, CERM, 10 uF, 25 V, +/- 20%, X5R, 0603", Cap_Case=0603, Manufacturer=TDK, PartNumber=C1608X5R1E106M080AC, Supplier Part Number 1=445-9015-1-ND, TempCo=X5R, Tolerance_%=20%, Value1="0.004639 ohm", Value2=25V, ValueDisplayed=10uF
C6 C9: library part CMP-0007158-5, "CAP, CERM, 22 uF, 10 V, +/- 20%, X5R, 0603", Cap_Case=0603, Manufacturer=MuRata, PartNumber=GRM187R61A226ME15D, Supplier Part Number 1=490-13243-1-ND, TempCo=X5R, Tolerance_%=20%, Value1=Unknown, Value2=10V, ValueDisplayed=22uF
C7: library part CMP-0006268-2, "CAP, CERM, 4.7 uF, 10 V, +/- 10%, X5R, 0402", Cap_Case=0402_065, Manufacturer=TDK, PartNumber=C1005X5R1A475K050BC, Supplier Part Number 1=445-13820-1-ND, TempCo=X5R, Tolerance_%=10%, Value1="0.003417 ohm", Value2=10V, ValueDisplayed=4.7uF
C8: library part CMP-0006222-2, "CAP, CERM, 2.2 uF, 10 V, +/- 20%, X5R, 0402", Cap_Case=0402, Manufacturer="Wurth Elektronik", Supplier Part Number 1=710-885012105013, TempCo=X5R, Tolerance_%=20%, Value1=Unknown, Value2=10V, ValueDisplayed=2.2uF
C10 C17: library part CMP-0006563-2, "CAP, CERM, 1 uF, 10 V, +/- 10%, X5R, 0402", Cap_Case=0402, Manufacturer=MuRata, PartNumber=GRM155R61A105KE15D, Supplier Part Number 1=490-3890-1-ND, TempCo=X5R, Tolerance_%=10%, Value1=Unknown, Value2=10V, ValueDisplayed=1uF
C11 C13 C14 C18 C20 C21 C23 C24: library part CMP-0006228-2, "CAP, CERM, 0.1 uF, 16 V, +/- 10%, X7R, 0402", Cap_Case=0402, Manufacturer="Wurth Elektronik", PartNumber=885012205037, Supplier Part Number 1=732-7532-1-ND, TempCo=X7R, Tolerance_%=10%, Value1=Unknown, Value2=16V, ValueDisplayed=0.1uF
C12 C15 C19 C22: library part CMP-0006776-4, "CAP, CERM, 220 pF, 50 V, +/- 1%, C0G/NP0, 0603", Cap_Case=0603, Manufacturer=AVX, PartNumber=06035A221FAT2A, Supplier Part Number 1=478-3719-1-ND, TempCo=C0G/NP0, Tolerance_%=1%, Value1="0.083 ohm", Value2=50V, ValueDisplayed=220pF
C16 C25: library part CMP-0006834-5, "CAP, CERM, 470 pF, 50 V, +/- 10%, X7R, 0603", Cap_Case=0603, Manufacturer="Wurth Elektronik", PartNumber=885012206081, Supplier Part Number 1=710-885012206081, TempCo=X7R, Tolerance_%=10%, Value1=Unknown, Value2=50V, ValueDisplayed=470pF
D1 D2: library part CMP-0005928-1, "Diode, TVS, Bi, 7 V, SOT-23", Manufacturer=Bourns, PartNumber=CDSOT23-SM712, Supplier Part Number 1=CDSOT23-SM712CT-ND, Value1=W
D3: library part CMP-0002946-2, "LED, Blue, SMD", Color=Blue, Manufacturer="Wurth Elektronik", PartNumber=150060BS75000, Power_TotalModule=105mW, Supplier Part Number 1=732-4966-1-ND, Value1=0.105W, Value2=3.2V
D4 D7 D8 D9: library part CMP-0002905-1, "LED, Green, SMD", Color=Green, Manufacturer="Wurth Elektronik", PartNumber=150060GS75000, Supplier Part Number 1=732-4971-1-ND, Value1=W, Value2=3.2V
D5: library part CMP-0002947-2, "LED, Red, SMD", Color=Red, Manufacturer="Wurth Elektronik", PartNumber=150060RS75000, Power_TotalModule=72mW, Supplier Part Number 1=732-4978-1-ND, Value1=0.072W, Value2=2V
D6: library part CMP-0029284-1, "Diode, Super Barrier Rectifier, 40 V, 3 A, AEC-Q101, PowerDI123", Manufacturer="Diodes Inc.", PartNumber=SBRT3U40P1-7, Supplier Part Number 1=SBRT3U40P1-7DICT-ND, Value1=3A, Value2=0.49V
FID1 FID2 FID3 FID4 FID5 FID6: library part CMP-0077181-1, "Fiducial mark.  There is nothing to buy or mount.", Manufacturer=N/A
J1: library part CMP-0065026-1, "Header, 2.54mm, 3x1, Tin, TH", Color=Black, Current_A=3A, Manufacturer=FCI, PartNumber=68001-403HLF, Supplier Part Number 1=609-3471-ND, Voltage_V=1.5kV
J2: library part CMP-0077259-1, "Receptacle, D-Sub, 15 Position, R/A, TH", Color=Black, Current_A=3A, Manufacturer="Wurth Elektronik", Supplier Part Number 1=16T0663, Voltage_V=125V
J3 J4: library part CMP-0075442-1, "Connector, Receptacle, 100mil, 10x2, Gold plated, TH", Manufacturer=Samtec, PartNumber=SSW-110-23-F-D
J5: library part CMP-0075046-1, "Power Jack, 2mm, R/A, SMD", Manufacturer=Switchcraft, PartNumber=RASM722X, Supplier Part Number 1=RASM722X-ND
J6: library part CMP-0054563-1, "Header, 100mil, 8x1, Tin, TH", Color=Black, Current_A=3A, Manufacturer="Sullins Connector Solutions", PartNumber=PEC08SAAN, Supplier Part Number 1=S1012E-08-ND, Voltage_V=1.8kV
J7 J8: library part CMP-0055834-1, "Jack, SMA, PCB, Gold, SMT", Manufacturer="Linx Technologies", PartNumber=CONSMA001-SMD-G, Supplier Part Number 1=CONSMA001-SMD-G-ND
L1: library part CMP-0064319-1, "Inductor, Shielded Drum Core, Metal Composite, 1 uH, 0.7 A, 0.1 ohm, SMD", Manufacturer="Wurth Elektronik", PartNumber=74479775210, Supplier Part Number 1=732-2952-1-ND, Value1="0.1 ohm", Value2=0.7A, ValueDisplayed=1uH
L2: library part CMP-0061137-1, "Inductor, Shielded, Composite, 2.2 uH, 1.6 A, 0.08 ohm, SMD", Manufacturer=Coilcraft, PartNumber=XFL3012-222MEB, Value1="0.08 ohm", Value2=1.6A, ValueDisplayed=2.2uH
LBL1: library part CMP-0003625-1, "Thermal Transfer Printable Labels, 0.650\" W x 0.200\" H - 10,000 per roll", Manufacturer=Brady, PartNumber=THT-14-423-10, Supplier Part Number 1=97C5133
Logo2: library part CMP-0074839-1
Logo3: library part CMP-0074847-1, "FCC_disclaimer"
R1: library part CMP-0018645-2, "RES, 2.2 M, 5%, 0.25 W, 1206", Manufacturer=Vishay-Dale, PartNumber=CRCW12062M20JNEA, Power_W=250mW, Supplier Part Number 1=541-2.2MECT-ND, TempCo="200 ppm/C", Tolerance_%=5%, Value2=0.25W, Value_Code=2M20, ValueDisplayed=2.2M
R2 R23 R31 R39 R45: library part CMP-0025697-4, "RES, 0, 5%, 0.1 W, AEC-Q200 Grade 0, 0603", Manufacturer=Vishay-Dale, PartNumber=CRCW06030000Z0EA, Power_W=100mW, Supplier Part Number 1=541-0.0GCT-ND, TempCo="200 ppm/C", Tolerance_%=5%, Value2=0.1W, Value_Code=0000, ValueDisplayed=0
R3: library part CMP-0026840-2, "RES, 150 k, 5%, 0.063 W, AEC-Q200 Grade 0, 0402", Manufacturer=Vishay-Dale, PartNumber=CRCW0402150KJNED, Power_W=63mW, Supplier Part Number 1=541-150KJCT-ND, TempCo="200 ppm/C", Tolerance_%=5%, Value2=0.063W, Value_Code=150k
R4 R5 R8 R13 R16 R26 R27 R30 R33 R44 R47: library part CMP-0026822-3, "RES, 0, 5%, 0.063 W, AEC-Q200 Grade 0, 0402", Manufacturer=Vishay-Dale, PartNumber=CRCW04020000Z0ED, Power_W=63mW, Supplier Part Number 1=541-0.0JCT-ND, TempCo="200 ppm/C", Tolerance_%=5%, Value2=0.063W, Value_Code=0000, ValueDisplayed=0
R6 R7 R25 R41: library part CMP-0026880-2, "RES, 22, 5%, 0.063 W, 0402", Manufacturer=Vishay-Dale, Power_W=63mW, Supplier Part Number 1=541-22JCT-ND, TempCo="200 ppm/C", Tolerance_%=5%, Value2=0.063W, Value_Code=22R0, ValueDisplayed=22
R9 R10 R17: library part CMP-0026890-5, "RES, 2.2 k, 5%, 0.063 W, AEC-Q200 Grade 0, 0402", Manufacturer=Vishay-Dale, PartNumber=CRCW04022K20JNED, Power_W=63mW, Supplier Part Number 1=541-2.2KJCT-ND, TempCo="200 ppm/C", Tolerance_%=5%, Value2=0.063W, Value_Code=2k20, ValueDisplayed=2.2k
R11 R20: library part CMP-0026938-5, "RES, 4.7 k, 5%, 0.063 W, AEC-Q200 Grade 0, 0402", Manufacturer=Vishay-Dale, PartNumber=CRCW04024K70JNED, Power_W=63mW, Supplier Part Number 1=541-4.7KJCT-ND, TempCo="200 ppm/C", Tolerance_%=5%, Value2=0.063W, Value_Code=4k70, ValueDisplayed=4.7k
R12 R19 R21: library part CMP-0026825-5, "RES, 10 k, 5%, 0.063 W, AEC-Q200 Grade 0, 0402", Manufacturer=Vishay-Dale, PartNumber=CRCW040210K0JNED, Power_W=63mW, Supplier Part Number 1=541-10KJCT-ND, TempCo="200 ppm/C", Tolerance_%=5%, Value2=0.063W, Value_Code=10k0, ValueDisplayed=10k
R14: library part CMP-0025729-4, "RES, 1.0 k, 5%, 0.1 W, AEC-Q200 Grade 0, 0603", Manufacturer=Vishay-Dale, PartNumber=CRCW06031K00JNEA, Power_W=100mW, Supplier Part Number 1=541-1.0KGCT-ND, TempCo="200 ppm/C", Tolerance_%=5%, Value2=0.1W, Value_Code=1k00, ValueDisplayed=1.0k
R15: library part CMP-0026903-3, "RES, 30 k, 5%, 0.063 W, AEC-Q200 Grade 0, 0402", Manufacturer=Vishay-Dale, PartNumber=CRCW040230K0JNED, Power_W=63mW, Supplier Part Number 1=541-30KJCT-ND, TempCo="200 ppm/C", Tolerance_%=5%, Value2=0.063W, Value_Code=30k0, ValueDisplayed=30k
R18: library part CMP-0025743-4, "RES, 1.0, 5%, 0.1 W, AEC-Q200 Grade 0, 0603", Manufacturer=Vishay-Dale, PartNumber=CRCW06031R00JNEA, Power_W=100mW, Supplier Part Number 1=541-1.0GCT-ND, TempCo="200 ppm/C", Tolerance_%=5%, Value2=0.1W, Value_Code=1R00, ValueDisplayed=1.0
R22 R32: library part CMP-0025729-4, "RES, 1.0 k, 5%, 0.1 W, AEC-Q200 Grade 0, 0603", Manufacturer=Vishay-Dale, Power_W=100mW, Supplier Part Number 1=541-1.0KGCT-ND, TempCo="200 ppm/C", Tolerance_%=5%, Value2=0.1W, Value_Code=1k00, ValueDisplayed=1.0k
R24 R34 R37 R40 R48 R49: library part CMP-0026938-4, "RES, 4.7 k, 5%, 0.063 W, 0402", Manufacturer=Vishay-Dale, Power_W=63mW, Supplier Part Number 1=541-4.7KJCT-ND, TempCo="200 ppm/C", Tolerance_%=5%, Value2=0.063W, Value_Code=4k70, ValueDisplayed=4.7k
R28 R29: library part CMP-0022009-5, "RES, 110, 1%, 0.1 W, AEC-Q200 Grade 0, 0603", Manufacturer=Vishay-Dale, Power_W=100mW, Supplier Part Number 1=541-110HCT-ND, TempCo="100 ppm/C", Tolerance_%=1%, Value2=0.1W, Value_Code=110R, ValueDisplayed=110
R35 R36 R50 R51: library part CMP-0026936-3, "RES, 47, 5%, 0.063 W, AEC-Q200 Grade 0, 0402", Manufacturer=Vishay-Dale, PartNumber=CRCW040247R0JNED, Power_W=63mW, Supplier Part Number 1=541-47JCT-ND, TempCo="200 ppm/C", Tolerance_%=5%, Value2=0.063W, Value_Code=47R0, ValueDisplayed=47
R38 R46: library part CMP-0025701-4, "RES, 10 k, 5%, 0.1 W, AEC-Q200 Grade 0, 0603", Manufacturer=Vishay-Dale, PartNumber=CRCW060310K0JNEA, Power_W=100mW, Supplier Part Number 1=541-10KGCT-ND, TempCo="200 ppm/C", Tolerance_%=5%, Value2=0.1W, Value_Code=10k0, ValueDisplayed=10k
R42 R43: library part CMP-0023196-3, "RES, 59.0, 1%, 0.1 W, 0603", Manufacturer="Yageo America", PartNumber=RC0603FR-0759RL, Power_W=100mW, Supplier Part Number 1=311-59.0HRCT-ND, TempCo="200 ppm/C", Tolerance_%=1%, Value2=0.1W, Value_Code=59R0, ValueDisplayed=59.0
TP1 TP2 TP3: library part CMP-0055138-1, "Test Point, Miniature, Black, TH", Color=Black, Manufacturer=Keystone, Supplier Part Number 1=36-5001-ND
U1: library part CMP-0073661-1, "2.7-18-V, 2-A, 79-mO On-Resistance Load Switch with Thermal Protection, DBV0006A (SOT-23-6)", Alternate Manufacturer="Texas Instruments", Alternate PartNumber=TPS22810DBVT, PartNumber=TPS22810DBVR
U2: library part CMP-0067211-1, "5V, 400mA, 4MHz Step-Up DC/DC Converter, YFF0006AEAE (DSBGA-6)", Alternate Manufacturer="Texas Instruments", Alternate PartNumber=TPS61240YFFT, PartNumber=TPS61240YFFR
U3: library part CMP-0037789-2, "Buck Step Down Regulator with 3 to 17 V Input and 3.3 V Output, -40 to 85 degC, 8-Pin WSON (DSG), Green (RoHS & no Sb/Br)", Manufacturer="Texas Instruments", PartNumber=TPS62162DSGR, Rating=Catalog, Switch Current Limit(Typ)(A)=1.8
U4 U7: library part CMP-0074780-2, "5-V RS-485 Transceivers With +/-16-kV IEC ESD Protection, DGK0008A (VSSOP-8)", Alternate Manufacturer="Texas Instruments", Alternate PartNumber=THVD1550DGK
U5 U6 U8: library part CMP-0051062-2, "Dual-Bit Dual Supply Transceiver with Configurable Voltage Translation and 3-State Outputs, YZP0008ADAD, LARGE T&R", F @ Nom Voltage(Max)(Mhz)=150, Generic Part Number=SN74LVC2T45, ICC @ Nom Voltage(Max)(mA)=0.004, Manufacturer="Texas Instruments", Operating Temperature Range(C)="-40 to 85", PartNumber=SN74LVC2T45YZPR, Rating=Military, tpd @ Nom Voltage(Max)(ns)=17.7,10.3,8.3,7.2, Voltage(Nom)(V)=1.8,2.5,3.3,5
ZZ1: library part CMP-0003616-3
ZZ2: library part CMP-0077236-1
ZZ3: library part CMP-0077237-1
ZZ4: library part CMP-0077238-1

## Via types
v1: diameter 20, hole 8, Top Layer to Bottom Layer, tented both sides, 371 vias
v2: diameter 20, hole 8, Top Layer to Bottom Layer, 51 vias
v3: diameter 32, hole 16, Top Layer to Bottom Layer, 9 vias
v4: diameter 20, hole 10, Top Layer to Bottom Layer, 3 vias
v5: diameter 19.68, hole 7.87, Top Layer to Bottom Layer, 2 vias

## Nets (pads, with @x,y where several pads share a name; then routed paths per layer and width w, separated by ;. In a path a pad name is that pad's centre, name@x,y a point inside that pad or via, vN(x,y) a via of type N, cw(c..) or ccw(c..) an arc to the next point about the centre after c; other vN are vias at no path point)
3V3: C6.1 C8.1 C14.2 C20.2 C24.2 L1.1 L2.2 R2.1 R12.2 R16.2 R17.2 R19.2 R48.2 R49.2 U2.A1 U3.6 U5.A2 U6.A1 U8.A2 | length 4940.3
  Top Layer w8: v4@565,1244 R49.2@606.38,1244 ; C14.2@616.61,1665.83 v2@616.61,1695 ; C24.2@688,1456 688,1430.12 ccw(c723.75,1430.12) U8.A2@698.47,1404.84 ; U6.A1@892.07,1558.89 cw(c932.28,1518.68) 932.28,1575.55 C20.2@936.54,1575.55
  Top Layer w10: C14.2@612.26,1668.77 ccw(c622.08,1678.59) 616.61,1665.83 ccw(c622.08,1678.59) 622.08,1664.7 U5.A2@662.96,1664.7 ; v2@878,338 R17.2@878,361.2 ; U3.6@1345.4,160.16 1375.84,160.16 cw(c1375.84,156) v2(1380,156) ; C6.1@1368,265 v2(1368,300)
  Top Layer w12: R48.2@287.15,1471.32 287.15,1499.87 v1(289.17,1501.89) ; C20.2@936.54,1575.55 936.54,1594.74 ccw(c919.47,1594.74) v2(931.54,1606.81) 931.54,1614.18 R12.2@984.56,1667.2 ; R19.2@1176,435.62 1176,437 cw(c1251,437) L1.1@1251,512
  Top Layer w14: C24.2@688,1456 C24.2@688,1461.23
  Top Layer w16: v2@528,1340.58 cw(c628,1340.58) 557.29,1411.29 v2@634.81,1488.81 ; v2(625.38,1488.81) v2@634.81,1488.81 ; C24.2@688.16,1461.07 688,1461.23 688,1461.69 660.88,1488.81 v2@634.81,1488.81
  Top Layer w20: 1478,520 R16.2@1478,488.62 1478,484 1496,484 cw(c1496,456) 1524,456
  Top Layer w25: R2.1@220,329 220,330 v3(275,330) ; L1.1@1253,511.5 cw(c1295.5,511.5) L1.1@1253,512 ; L1.1@1267.37,511.04 cw(c1310.38,510.53) 1310.38,553.54 ; 1313.4,553.94 1444,554 cw(c1444,520) 1478,520 ; v3(1452,324) ccw(c1460,324) 1460,316 1500,316 ccw(c1500,340) 1524,340 1524,456
  Signal Layer 1 w10: v2@878,338 892,324
  Signal Layer 1 w12: 616.43,1623 896.09,1623 ; 895.03,1622.74 915.61,1622.74 v2(931.54,1606.81)
  Signal Layer 1 w16: 616.17,1621.03 v2@616.17,1695 ; 616.43,1623 616.43,1497.3 v2@626.13,1487.6
  Signal Layer 1 w25: v3(275,330) 273.37,330 cw(c273.37,275.37) 312,314 ccw(c350.63,352.63) 350.63,298 838.58,298 ccw(c838.58,398) 894.62,315.18 ccw(c838.58,398) 909.29,327.29 930,348 cw(c958.97,319.03) 958.97,360 960.58,361.61 987.4,361.61 988.46,360.55 1013.73,360.55 1014.8,361.61 1217.26,361.61 1217.37,361.5 1243.63,361.5 1243.74,361.61 1336.79,361.61 1360.33,385.16 1426.86,385.16 1452,360.01 v3(1452,324)
  Signal Layer 2 w8: 536,1244 v4@565,1244
  Signal Layer 2 w10: v2(1368,300) 1368,298 cw(c1368,286) 1380,286 v2(1380,156)
  Signal Layer 2 w12: v1(289.17,1501.89) 405.3,1501.89 528,1379.19 v2@528,1340.58
  Signal Layer 2 w16: v3(275,330) 275,381.92 cw(c379,381.92) 305.43,455.43 550.71,700.71 ccw(c480,771.42) 580,771.42 580,938.64 ccw(c480,938.64) 550.71,1009.35 535.03,1025.03 cw(c552,1042) 528,1042 v2@528,1340.58
  other v2: 881.01,334.26 528.96,1346.73 615.51,1695
  other v4: 559.93,1244.3
3V3_EN_CLK: J3.17 R49.1 U8.C2 | length 1632
  Top Layer w8: R49.1@653.62,1244 653.62,1222.4 ccw(c663.33,1222.4) 656.46,1215.54 v4@669,1203 ; v2(714,1472) 715.17,1472 cw(c715.17,1465.17) 719.99,1470.01 731.27,1458.73 cw(c700.54,1428) 744,1428 U8.C2@737.84,1404.84
  Signal Layer 2 w10: v2(714,1472) cw(c714,1462.34) 720.83,1469.17 731.27,1458.73 cw(c700.54,1428) 744,1428 cw(c698.21,1428) 730.59,1395.62 674.97,1340 ccw(c711.11,1303.86) 660,1303.86 660,1230.56 ccw(c697.56,1230.56) 671,1204 cw(c615.47,1148.47) 694,1148.47 694,1144 ccw(c742.28,1144) 708.14,1109.86 878.71,939.29 cw(c808,868.58) 908,868.58 908,210.53 ccw(c1008,210.53) 937.29,139.82 J3.17@958.49,118.62
  other v4: 670.52,1204.15
3V3_EN_TX: J4.7 R37.2 U5.C2 | length 367.7
  Top Layer w10: v1(699.2,1706.69) 709.54,1717.03 R37.2@731.15,1717.03 ; U5.C2@702.33,1664.7 v1@702.33,1702.57
  Signal Layer 2 w10: J4.7@458.52,1819.62 492.85,1785.29 ccw(c563.56,1856) 563.56,1756 657.76,1756 cw(c657.76,1732.25) 674.56,1749.04 cw(c655.04,1729.52) 682.65,1729.52 682.65,1726.07 ; 682.66,1728.41 682.66,1723.23 v1(699.2,1706.69)
3V3_ENABLE_5V: J4.20 R19.1 R21.2 U2.C1 | length 1960.7
  Top Layer w10: R21.2@1124,387.62 1174.62,387.62 R19.1@1175,388 ; R19.1@1176,389 1179,392 v2(1231,392) 1279.03,392 ccw(c1279.03,432.97) 1308,404 1319.38,415.38 ccw(c1305.51,429.25) U2.C1@1325.13,429.25
  Signal Layer 1 w10: v2(1005,895) ccw(c944.64,955.36) 1030,955.36 1030,1276.89 ccw(c954.89,1276.89) v2(1008,1330)
  Signal Layer 2 w10: v2(1005,895) 1005,492 ccw(c1105,492) 1105,392 v2(1231,392) ; v2(1008,1330) 1008,1844 cw(c1068.59,1844) 1025.75,1886.84 J4.20@1058.52,1919.62
3V3_ENC_PWR_EN: J4.18 R13.1 | length 418.2
  Top Layer w10: R13.1@1086.13,1719.76 1090.72,1724.35 v1(1090.72,1755.98)
  Signal Layer 2 w10: J4.18@958.52,1919.62 979.23,1940.33 cw(c1049.94,1869.62) 1049.94,1969.62 1068.38,1969.62 cw(c1068.38,1924) 1114,1924 1114,1778.93 v1@1087.78,1752.71
3V3_RX_CLK: R7.1 U6.C1 | length 588.8
  Top Layer w8: 842.11,1598.85 852.7,1588.27 U6.C1@852.7,1558.89
  Top Layer w10: R7.1@474.3,1644.02 474.94,1644.66 v1(517,1644.66) ; v1@810.93,1677.57 810.93,1630.04 842.11,1598.85
  Signal Layer 1 w10: v1@517.3,1644.43 535.56,1662.68 535.56,1737.13 552.9,1754.48 645.38,1754.48 668.62,1731.24 755.46,1731.24 v1(807.02,1679.68)
3V3_RX_DATA: J4.12 U6.B1 | length 481.2
  Top Layer w10: v1@860.59,1720.31 cw(c832.12,1691.84) 872.38,1691.84 U6.B1@872.38,1558.89
  Signal Layer 2 w10: J4.12@661.11,1912.82 678.37,1895.56 ccw(c749.08,1966.27) 749.08,1866.27 780.63,1866.27 cw(c780.63,1840.5) 798.85,1858.72 cw(c773.4,1833.27) 809.4,1833.27 809.4,1814.24 ; 809.42,1816.67 809.42,1786.98 ccw(c846.55,1786.98) 820.3,1760.72 v1(859.7,1721.31)
3V3_TX_CLK: J1.3 J4.1 R48.1 U8.B2 | length 1265.6
  Top Layer w8: v2(718,1434) 718.16,1433.84 U8.B2@718.16,1404.84
  Top Layer w10: J1.3@165.1,1470.24 166.18,1471.32 R48.1@247.15,1471.32
  Signal Layer 2 w10: J1.3@158,1470 cw(c158,1517.5) 110.5,1517.5 110.5,1730.18 cw(c210.5,1730.18) 139.79,1800.89 158.52,1819.62 198.85,1779.29 ccw(c269.56,1850) 269.56,1750 460.58,1750 cw(c460.58,1650) 531.29,1720.71 595.13,1656.87 ; 594.68,1657.92 cw(c528.64,1591.87) 622.04,1591.87 ; 621.91,1571.68 621.91,1591.57 ; 622,1571.42 ccw(c722,1571.42) 651.29,1500.71 v2(718,1434)
3V3_TX_DATA: R6.2 R34.1 U5.B2 | length 91.3
  Top Layer w10: R34.1@620.58,1731.5 643.89,1708.19 R6.2@650.59,1708.19 ; R6.2@660.95,1704.82 669.62,1696.15 cw(c638.17,1664.7) U5.B2@682.45,1668.88 ; U5.B2@682.45,1664.48 U5.B2@682.45,1668.88 ; U5.B2@682.65,1664.7 ccw(c638.17,1664.7) U5.B2@682.45,1668.88
5V: C9.1 C10.1 C11.1 C13.2 C17.1 C18.1 C21.2 C23.2 R18.2 R22.2 R24.2 R38.2 R40.2 U4.8 U5.A1 U6.A2 U7.8 U8.A1 | length 5004.1
  Top Layer w8: C23.2@688,1334 688,1359.87 cw(c723.76,1359.87) U8.A1@698.47,1385.16 ; U6.A2@892.07,1539.21 ccw(c931.07,1578.22) 931.07,1523.05 C21.2@936.54,1523.05
  Top Layer w10: v2(582.82,1603.69) C13.2@634.46,1603.69 ; C13.2@645.21,1603.48 662.96,1621.23 U5.A1@662.96,1645.02 ; v2@1723.62,1031.05 1723.85,1030.82 R40.2@1789.43,1030.82 ; v2@1725,1055.56 1758.97,1089.52 1758.97,1141.09 R24.2@1774.43,1156.56 ; v2@2102,1261.76 v2(2102,1262) ; v2(2304,808) R38.2@2304,842.33 ; v2(2304,1064) R22.2@2304,1092
  Top Layer w12: v2(936.54,1490.05) C21.2@936.54,1523.05
  Top Layer w14: v2(688,1304.68) C23.2@688,1334
  Top Layer w16: U7.8@2045.6,958.39 cw(c2045.6,970.99) 2033,970.99 C17.1@2033,1010 C18.1@2073,1010 v2(2110,1010) ; U4.8@2045.6,1210.38 cw(c2045.6,1223.98) 2032,1223.98 C11.1@2032,1261.76 C10.1@2072,1261.76 v2@2102,1261.76
  Signal Layer 1 w10: 1740,1051.18 2132,1051.18 ; 2201.9,1089 2283.56,1089 cw(c2283.56,1065.56) v2@2307,1065.56 ; 2203.17,1089.22 ccw(c2203.17,1036.22) 2165.7,1073.7 2151.09,1059.09 cw(c2132,1078.18) 2132,1051.18 ; v2(2304,808) 2304,757 cw(c2284,757) 2284,737 2212,737 cw(c2212,793) 2156,793 2156,1027.18 ccw(c2132,1027.18) 2132,1051.18 ; v2(2304,1064) v2@2304.02,1064.28
  Signal Layer 1 w12: 582,1620 582,1706.42 596.82,1721.24 632.13,1721.24 653.09,1700.28 ; 654.04,1699.02 673.9,1679.17 673.9,1653.79 682.02,1645.67 ; 680.1,1647.51 683.46,1644.14 829.21,1644.14 829.42,1643.93 849.3,1643.93 849.51,1644.14 928.19,1644.14 ; 928.05,1644.05 cw(c928.05,1623.57) 942.54,1638.05 942.69,1637.9 cw(c906.84,1602.05) 957.54,1602.05 957.54,1540.75 cw(c885.84,1540.75) v2(936.54,1490.05)
  Signal Layer 1 w16: 582,1620 582,1445.29 617.01,1410.28 617.01,1305.69 ; 616.82,1305.14 616.82,1305.42 v2@688,1305.42 ; v2(1724,1030) 2090,1030 v2(2110,1010) v2@2111.19,1008.81 ; 1736,1070 1906,1070 ccw(c1906,1122) 1958,1122 1958,1230.99 cw(c1989.01,1230.99) 1989.01,1262 v2(2102,1262)
  Signal Layer 1 w20: v3(1500,1046) 1653.17,1046
  Signal Layer 2 w20: v2(688,1304.68) 686,1279.42 ccw(c786,1279.42) 715.29,1208.71 737.45,1186.55 cw(c699.89,1149) 753,1149 ccw(c856,1149) 809.63,1057.03 ccw(c856,1149) 856,1046 v3(1500,1046)
  other v2: 1652,1030 1724,1056 1652,1058
5VUNFILTERED: C7.1 R16.1 R18.1 R20.2 U2.B2 U2.C2 | length 2154.4
  Top Layer w10: R20.2@958,361.2 971.2,361.2 ccw(c971.2,390) v2@1000,390 ; U2.C2@1340.87,429.25 1355.64,414.49 ccw(c1380.96,439.81) 1380.96,404 1390,404 ccw(c1390,424) 1410,424 1410,432
  Top Layer w20: 1415,446 R16.1@1478,446 ; v3(1479,386) R16.1@1479,445
  Top Layer w26: v3(1640,968) R18.1@1690,968
  Signal Layer 1 w10: v2@1000,390 1196,390 ccw(c1196,402) 1208,402 cw(c1226,402) 1226,420 1422,420 ccw(c1422,430) 1432,430 v2(1432,438)
  Signal Layer 1 w26: v3(1116,892) cw(c1192,892) 1192,968 v3(1640,968)
  Signal Layer 2 w26: v3(1116,892) 1116,570 ccw(c1216,570) 1216,470 1410,470 cw(c1410,402) 1478,402 1479,401 v3(1479,386)
  other v2: 1001.1,391.05
CLK_N: C22.1 D1.1 J6.7 R4.2 R43.2 R45.2 R46.2 | length 565.9
  Top Layer w10: v2(2342,936) v2@2342,936.16 ; J6.7@2543.41,796.7 cw(c2543.41,696.7) 2614.12,767.41 ; 2614.82,767.43 R4.2@2637.12,745.12
  Top Layer w14: R45.2@2154,946 2163.84,936.16 R43.2@2193.73,936.16 C22.1@2248.73,936.16 R46.2@2303.73,936.16 v2@2336,936.16
  Signal Layer 2 w10: v2@2336,936 v2(2342,936) v2@2350.28,936 ; v2@2346.42,935.77 cw(c2346.42,835.77) 2417.13,906.49 J6.7@2525.63,797.98
  Bottom Layer w12: v2(2342,936) D1.1@2353.24,956.4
